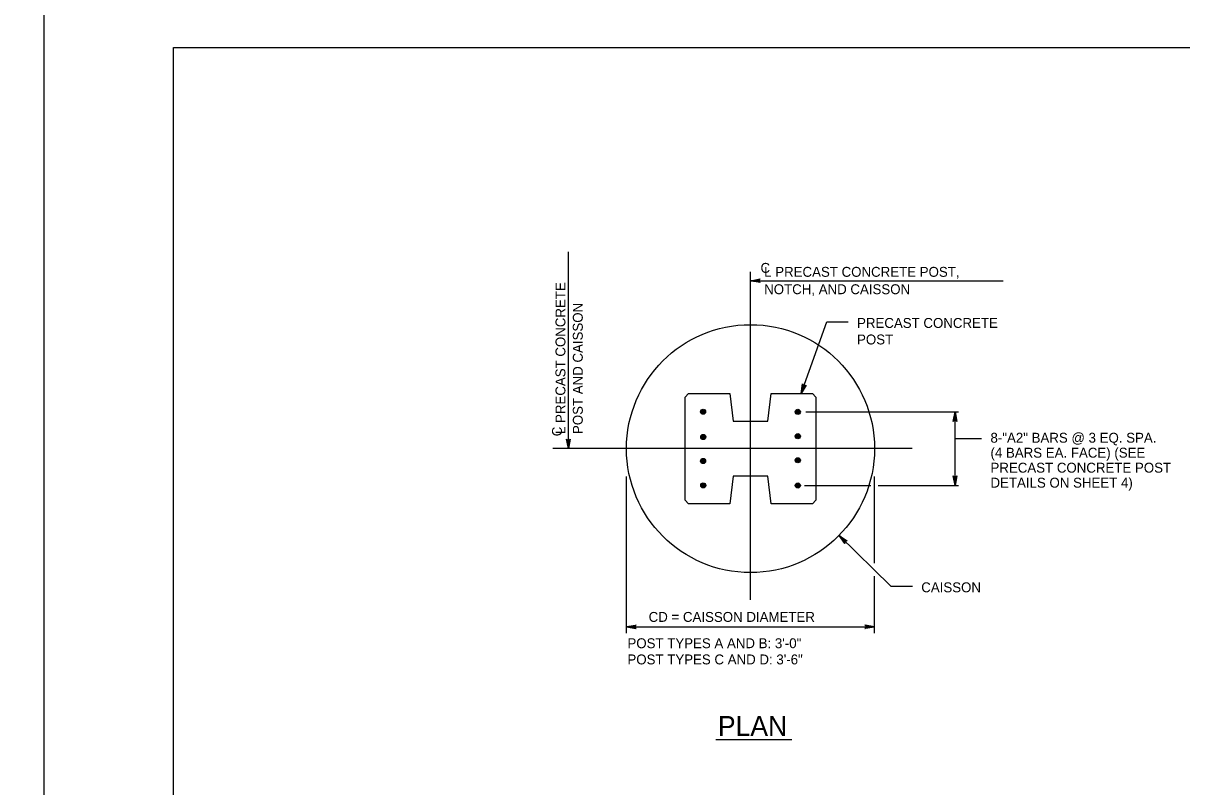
# Model space of a CAD drawing. Extents: x 3351 to 8430, y -3586 to 1457.
# Drawn here: x 3754.8 to 4113.6, y -1454.4 to -1217.8 of the extents above; entities that cross this region are included whole.
import ezdxf

# ---------------------------------------------------------------- set-up
doc = ezdxf.new("R2010")
doc.units = 0
for name, color, linetype in [('1', 7, 'Continuous'), ('2', 7, 'Continuous'), ('PLT-BNDY', 7, 'Continuous')]:
    doc.layers.add(name, color=color, linetype=linetype)

msp = doc.modelspace()

# ---------------------------------------------------------------- linework, layer by layer
at = {"layer": '1'}
for p, q in [((3923.64, -1349.62), (3923.64, -1288.65)), ((3980.03, -1396.44), (3980.03, -1294.86)), ((3980.03, -1297.59), (4058.29, -1297.59)), ((3995.69, -1332.55), (4003.64, -1310.32)), ((4003.64, -1310.32), (4010.29, -1310.32)), ((3959.77, -1333.63), (3960.84, -1332.55)), ((3959.77, -1365.62), (3959.77, -1333.63)), ((3960.84, -1332.55), (3973.63, -1332.55)), ((3973.63, -1332.55), (3974.7, -1341.08)), ((3985.37, -1341.08), (3986.43, -1332.55)), ((3986.43, -1332.55), (3999.24, -1332.55)), ((3999.24, -1332.55), (4000.3, -1333.63)), ((4000.3, -1333.63), (4000.3, -1365.62)), ((3974.7, -1341.08), (3985.37, -1341.08)), ((3997.14, -1338.23), (4044.38, -1338.23)), ((4043.36, -1361.04), (4043.36, -1338.23)), ((4043.36, -1346.44), (4051.5, -1346.44)), ((4030.07, -1349.62), (3918.88, -1349.62)), ((3941.63, -1406.76), (3941.63, -1358.26)), ((3974.7, -1358.15), (3973.63, -1366.68)), ((3985.37, -1358.15), (3974.7, -1358.15)), ((3986.43, -1366.68), (3985.37, -1358.15)), ((4018.43, -1385.13), (4018.43, -1358.26)), ((3996.74, -1361.04), (4017.28, -1361.04)), ((4019.51, -1361.04), (4044.38, -1361.04)), ((3960.84, -1366.68), (3959.77, -1365.62)), ((3973.63, -1366.68), (3960.84, -1366.68)), ((3999.23, -1366.68), (3986.43, -1366.68)), ((4000.3, -1365.62), (3999.23, -1366.68)), ((4007.47, -1376.49), (4023.52, -1392.22)), ((4018.43, -1406.76), (4018.43, -1389.15)), ((4023.52, -1392.22), (4030.17, -1392.22)), ((3941.63, -1404.82), (4018.43, -1404.82)), ((3969.28, -1439.74), (3992.81, -1439.74))]:
    msp.add_line(p, q, dxfattribs=at)
for points in [[(3980.03, -1297.59), (3983.02, -1297.03), (3982.79, -1297.19), (3982.67, -1297.39), (3982.63, -1297.59), (3982.67, -1297.79), (3982.79, -1297.99), (3983.02, -1298.15), (3980.03, -1297.59), (3982.79, -1297.99), (3982.67, -1297.79), (3980.03, -1297.59), (3982.63, -1297.59), (3982.67, -1297.39), (3980.03, -1297.59), (3982.79, -1297.19)], [(3995.69, -1332.55), (3996.17, -1329.55), (3996.24, -1329.82), (3996.39, -1330), (3996.57, -1330.1), (3996.77, -1330.14), (3997, -1330.09), (3997.22, -1329.93), (3995.69, -1332.55), (3997, -1330.09), (3996.77, -1330.14), (3995.69, -1332.55), (3996.57, -1330.1), (3996.39, -1330), (3995.69, -1332.55), (3996.24, -1329.82)], [(4043.36, -1338.23), (4043.92, -1341.21), (4043.84, -1341.09), (4043.76, -1340.98), (4043.66, -1340.92), (4043.56, -1340.86), (4043.46, -1340.84), (4043.36, -1340.83), (4043.26, -1340.84), (4043.16, -1340.86), (4043.06, -1340.92), (4042.96, -1340.98), (4042.88, -1341.09), (4042.8, -1341.21), (4043.36, -1338.23), (4042.88, -1341.09), (4042.96, -1340.98), (4043.36, -1338.23), (4043.06, -1340.92), (4043.16, -1340.86), (4043.36, -1338.23), (4043.26, -1340.84), (4043.36, -1340.83), (4043.36, -1338.23), (4043.46, -1340.84), (4043.56, -1340.86), (4043.36, -1338.23), (4043.66, -1340.92), (4043.76, -1340.98), (4043.36, -1338.23), (4043.84, -1341.09)], [(3923.64, -1349.62), (3923.08, -1346.64), (3923.24, -1346.87), (3923.44, -1346.99), (3923.64, -1347.02), (3923.84, -1346.99), (3924.04, -1346.87), (3924.2, -1346.64), (3923.64, -1349.62), (3924.04, -1346.87), (3923.84, -1346.99), (3923.64, -1349.62), (3923.64, -1347.02), (3923.44, -1346.99), (3923.64, -1349.62), (3923.24, -1346.87)], [(4043.36, -1361.04), (4042.8, -1358.06), (4042.88, -1358.17), (4042.96, -1358.29), (4043.06, -1358.34), (4043.16, -1358.4), (4043.26, -1358.42), (4043.36, -1358.44), (4043.46, -1358.42), (4043.56, -1358.4), (4043.66, -1358.34), (4043.76, -1358.29), (4043.84, -1358.17), (4043.92, -1358.06), (4043.36, -1361.04), (4043.84, -1358.17), (4043.76, -1358.29), (4043.36, -1361.04), (4043.66, -1358.34), (4043.56, -1358.4), (4043.36, -1361.04), (4043.46, -1358.42), (4043.36, -1358.44), (4043.36, -1361.04), (4043.26, -1358.42), (4043.16, -1358.4), (4043.36, -1361.04), (4043.06, -1358.34), (4042.96, -1358.29), (4043.36, -1361.04), (4042.88, -1358.17)], [(4007.47, -1376.49), (4009.99, -1378.18), (4009.71, -1378.13), (4009.49, -1378.19), (4009.32, -1378.31), (4009.21, -1378.48), (4009.15, -1378.7), (4009.21, -1378.98), (4007.47, -1376.49), (4009.15, -1378.7), (4009.21, -1378.48), (4007.47, -1376.49), (4009.32, -1378.31), (4009.49, -1378.19), (4007.47, -1376.49), (4009.71, -1378.13)], [(3941.63, -1404.82), (3944.62, -1404.26), (3944.5, -1404.34), (3944.39, -1404.42), (3944.33, -1404.52), (3944.27, -1404.62), (3944.25, -1404.72), (3944.23, -1404.82), (3944.25, -1404.92), (3944.27, -1405.02), (3944.33, -1405.12), (3944.39, -1405.22), (3944.5, -1405.3), (3944.62, -1405.38), (3941.63, -1404.82), (3944.5, -1405.3), (3944.39, -1405.22), (3941.63, -1404.82), (3944.33, -1405.12), (3944.27, -1405.02), (3941.63, -1404.82), (3944.25, -1404.92), (3944.23, -1404.82), (3941.63, -1404.82), (3944.25, -1404.72), (3944.27, -1404.62), (3941.63, -1404.82), (3944.33, -1404.52), (3944.39, -1404.42), (3941.63, -1404.82), (3944.5, -1404.34)], [(4018.43, -1404.82), (4015.45, -1405.38), (4015.57, -1405.3), (4015.68, -1405.22), (4015.74, -1405.12), (4015.8, -1405.02), (4015.82, -1404.92), (4015.83, -1404.82), (4015.82, -1404.72), (4015.8, -1404.62), (4015.74, -1404.52), (4015.68, -1404.42), (4015.57, -1404.34), (4015.45, -1404.26), (4018.43, -1404.82), (4015.57, -1404.34), (4015.68, -1404.42), (4018.43, -1404.82), (4015.74, -1404.52), (4015.8, -1404.62), (4018.43, -1404.82), (4015.82, -1404.72), (4015.83, -1404.82), (4018.43, -1404.82), (4015.82, -1404.92), (4015.8, -1405.02), (4018.43, -1404.82), (4015.74, -1405.12), (4015.68, -1405.22), (4018.43, -1404.82), (4015.57, -1405.3)]]:
    msp.add_lwpolyline(points, dxfattribs=at)
for centre, radius in [((3980.03, -1349.62), 38.4), ((3965.35, -1338.19), 0.798), ((3965.35, -1338.19), 0.604), ((3965.35, -1338.19), 0.432), ((3965.35, -1338.19), 0.245), ((3994.67, -1338.23), 0.798), ((3994.67, -1338.23), 0.604), ((3994.67, -1338.23), 0.432), ((3994.67, -1338.23), 0.245), ((3965.35, -1338.19), 0.0575), ((3994.67, -1338.23), 0.0575), ((3965.41, -1346.01), 0.798), ((3994.67, -1345.77), 0.798), ((3994.67, -1345.77), 0.604), ((3965.41, -1346.01), 0.604), ((3965.41, -1346.01), 0.432), ((3965.41, -1346.01), 0.245), ((3965.41, -1346.01), 0.0575), ((3994.67, -1345.77), 0.432), ((3994.67, -1345.77), 0.245), ((3994.67, -1345.77), 0.0575), ((3965.35, -1353.46), 0.798), ((3965.35, -1353.46), 0.604), ((3965.35, -1353.46), 0.432), ((3965.35, -1353.46), 0.245), ((3965.35, -1353.46), 0.0575), ((3994.67, -1353.22), 0.798), ((3994.67, -1353.22), 0.604), ((3994.67, -1353.22), 0.432), ((3994.67, -1353.22), 0.245), ((3994.67, -1353.22), 0.0575), ((3965.41, -1361), 0.798), ((3965.41, -1361), 0.604), ((3965.41, -1361), 0.432), ((3965.41, -1361), 0.245), ((3965.41, -1361), 0.0575), ((3994.67, -1361.04), 0.798), ((3994.67, -1361.04), 0.604), ((3994.67, -1361.04), 0.432), ((3994.67, -1361.04), 0.245), ((3994.67, -1361.04), 0.0575)]:
    msp.add_circle(centre, radius, dxfattribs=at)
at = {"layer": '2'}
for p, q in [((3801.34, -1789.31), (3801.34, -1225.31)), ((3801.34, -1225.31), (4587.34, -1225.31))]:
    msp.add_line(p, q, dxfattribs=at)
at = {"layer": 'PLT-BNDY'}
msp.add_lwpolyline([(3761.34, -1210.31), (4602.34, -1210.31), (4602.34, -1804.31), (3761.34, -1804.31)], close=True, dxfattribs=at)

# ---------------------------------------------------------------- texts
at = {"layer": '1'}
for s, height, p in [('C', 3.07, (3983.13, -1295.16)), ('L PRECAST CONCRETE POST,', 3.072, (3984.26, -1296.39)), ('NOTCH, AND CAISSON', 3.072, (3984.26, -1301.77)), ('PRECAST CONCRETE', 3.072, (4013.02, -1312.22)), ('POST', 3.072, (4013.02, -1317.34)), ('8-"A2" BARS @ 3 EQ. SPA.', 3.072, (4054.33, -1347.78)), ('(4 BARS EA. FACE) (SEE', 3.072, (4054.33, -1352.42)), ('PRECAST CONCRETE POST', 3.072, (4054.33, -1357.06)), ('DETAILS ON SHEET 4)', 3.072, (4054.33, -1361.7)), ('11', 230.4, (3440.24, -1615.21)), ('CAISSON', 3.072, (4032.9, -1394.12)), ('CD = CAISSON DIAMETER', 3.072, (3948.5, -1403.29)), ('POST TYPES A AND B: 3\'-0"', 3.072, (3941.93, -1411.44)), ('POST TYPES C AND D: 3\'-6"', 3.072, (3941.93, -1416.46)), ('PLAN', 6.144, (3969.93, -1438.6))]:
    msp.add_text(s, height=height, dxfattribs=at).set_placement(p)
for s, height, p in [('L PRECAST CONCRETE', 3.072, (3922.73, -1345.09)), ('POST AND CAISSON', 3.072, (3928.1, -1345.09)), ('C', 3.07, (3921.65, -1345.79))]:
    msp.add_text(s, height=height, rotation=90, dxfattribs=at).set_placement(p)

doc.saveas('drawing.dxf')
